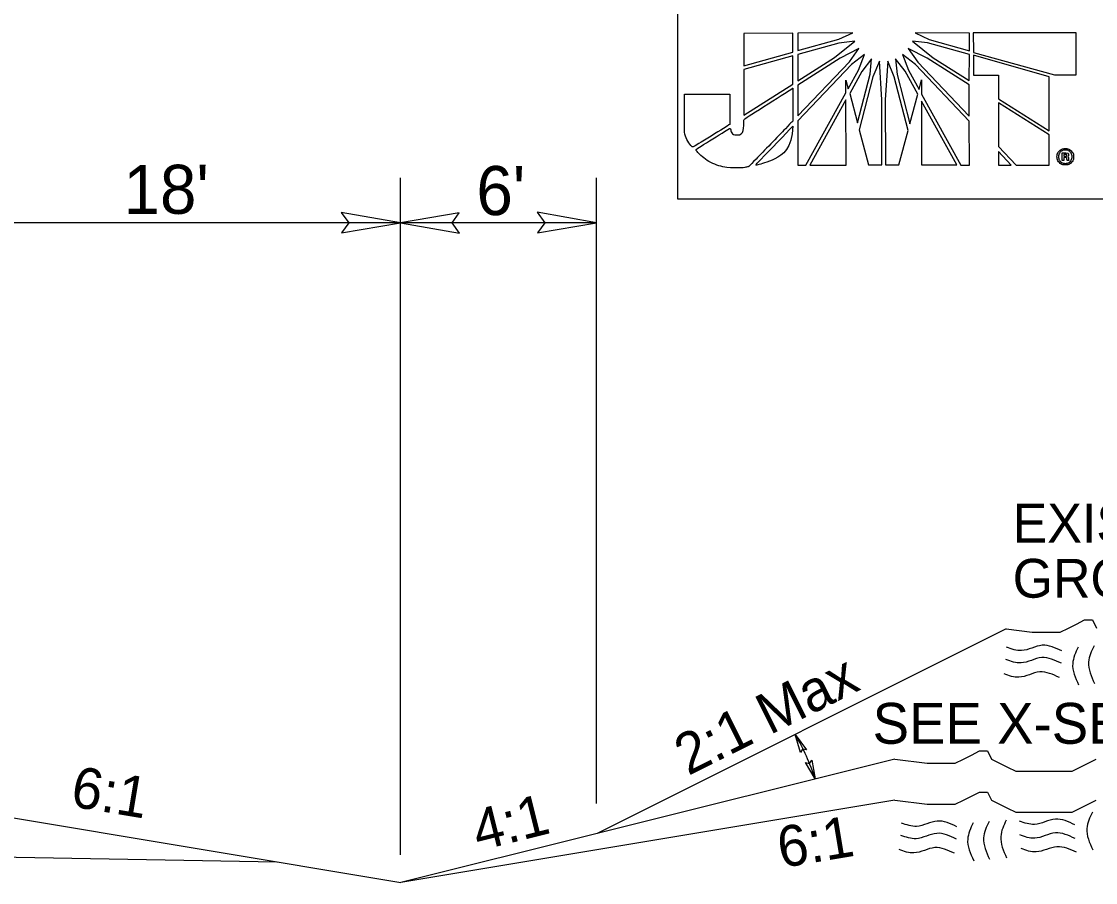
# Model space of a CAD drawing. Extents: x 2294455 to 2294795, y 719276 to 719941.
# Drawn here: x 2294722.83 to 2294763.9, y 719649.46 to 719682.39 of the extents above; entities that cross this region are included whole.
import ezdxf

# ---------------------------------------------------------------- set-up
doc = ezdxf.new("R2010")
doc.units = 0
for name, color, linetype in [('Old_Level_1', 7, 'Continuous'), ('Old_Level_11', 7, 'Continuous'), ('Old_Level_2', 7, 'Continuous'), ('Old_Level_3', 7, 'Continuous'), ('Typical Hinge Slope Arterial CELL', 7, 'Continuous'), ('Typical Hinge Slope Interstate CELL', 7, 'Continuous'), ('Typical Terminator CELL', 7, 'Continuous')]:
    doc.layers.add(name, color=color, linetype=linetype)

msp = doc.modelspace()

# ---------------------------------------------------------------- linework, layer by layer
at = {"layer": 'Old_Level_1'}
for p, q in [((2294752.321, 719681.935), (2294750.449, 719681.933)), ((2294750.449, 719681.933), (2294750.45, 719680.691)), ((2294752.322, 719681.212), (2294752.321, 719681.935)), ((2294754.623, 719681.947), (2294752.516, 719681.945)), ((2294752.516, 719681.945), (2294752.517, 719681.274)), ((2294752.517, 719681.274), (2294754.086, 719681.708)), ((2294754.086, 719681.708), (2294754.623, 719681.947)), ((2294759.084, 719681.942), (2294757.008, 719681.949)), ((2294757.008, 719681.949), (2294757.534, 719681.702)), ((2294757.534, 719681.702), (2294759.085, 719681.268)), ((2294759.085, 719681.268), (2294759.084, 719681.942)), ((2294763.165, 719681.955), (2294759.229, 719681.951)), ((2294759.229, 719681.951), (2294759.23, 719681.228)), ((2294763.167, 719680.342), (2294763.165, 719681.955)), ((2294754.086, 719681.563), (2294752.517, 719681.129)), ((2294753.923, 719681.007), (2294754.697, 719681.638)), ((2294754.697, 719681.638), (2294754.086, 719681.563)), ((2294754.852, 719681.348), (2294754.139, 719680.985)), ((2294754.491, 719680.84), (2294754.852, 719681.348)), ((2294756.74, 719681.349), (2294757.102, 719680.834)), ((2294757.463, 719680.989), (2294756.74, 719681.349)), ((2294756.903, 719681.64), (2294757.689, 719680.998)), ((2294757.481, 719681.566), (2294756.903, 719681.64)), ((2294759.085, 719681.126), (2294757.481, 719681.566)), ((2294750.45, 719680.691), (2294752.322, 719681.212)), ((2294752.322, 719681.076), (2294750.45, 719680.549)), ((2294752.323, 719679.992), (2294752.322, 719681.076)), ((2294752.517, 719681.129), (2294752.518, 719680.116)), ((2294752.518, 719680.116), (2294753.923, 719681.007)), ((2294754.139, 719680.985), (2294752.518, 719679.952)), ((2294755.069, 719681.122), (2294754.572, 719680.739)), ((2294754.841, 719680.523), (2294755.069, 719681.122)), ((2294755.338, 719680.956), (2294754.967, 719680.479)), ((2294755.286, 719680.378), (2294755.338, 719680.956)), ((2294755.647, 719680.872), (2294755.391, 719680.273)), ((2294755.728, 719679.396), (2294755.647, 719680.872)), ((2294755.956, 719680.873), (2294755.861, 719679.396)), ((2294756.203, 719680.274), (2294755.956, 719680.873)), ((2294756.255, 719680.956), (2294756.318, 719680.357)), ((2294756.617, 719680.481), (2294756.255, 719680.956)), ((2294756.521, 719681.124), (2294756.75, 719680.524)), ((2294757.018, 719680.741), (2294756.521, 719681.124)), ((2294759.074, 719679.967), (2294757.463, 719680.989)), ((2294757.689, 719680.998), (2294759.074, 719680.134)), ((2294759.074, 719680.134), (2294759.085, 719681.126)), ((2294759.23, 719681.228), (2294759.23, 719681.206)), ((2294759.23, 719681.206), (2294762.33, 719680.341)), ((2294759.23, 719681.095), (2294759.23, 719681.083)), ((2294762.132, 719680.27), (2294759.23, 719681.095)), ((2294759.23, 719681.083), (2294759.231, 719680.329)), ((2294750.45, 719680.549), (2294750.452, 719678.804)), ((2294752.519, 719678.784), (2294754.491, 719680.84)), ((2294754.572, 719680.739), (2294752.519, 719678.586)), ((2294754.449, 719679.809), (2294754.841, 719680.523)), ((2294754.967, 719680.479), (2294754.502, 719679.632)), ((2294757.103, 719679.604), (2294756.617, 719680.481)), ((2294756.75, 719680.524), (2294757.152, 719679.78)), ((2294759.075, 719678.574), (2294757.018, 719680.741)), ((2294757.102, 719680.834), (2294759.075, 719678.769)), ((2294754.356, 719679.654), (2294754.356, 719680.148)), ((2294754.356, 719680.148), (2294754.449, 719679.809)), ((2294754.802, 719678.508), (2294755.286, 719680.378)), ((2294755.391, 719680.273), (2294754.864, 719678.249)), ((2294756.743, 719678.22), (2294756.203, 719680.274)), ((2294756.318, 719680.357), (2294756.804, 719678.467)), ((2294757.152, 719679.78), (2294757.248, 719680.151)), ((2294757.248, 719680.151), (2294757.248, 719679.604)), ((2294759.231, 719680.329), (2294760.192, 719680.33)), ((2294760.192, 719680.33), (2294760.193, 719679.431)), ((2294762.134, 719678.203), (2294762.132, 719680.27)), ((2294762.33, 719680.341), (2294763.167, 719680.342)), ((2294750.452, 719678.804), (2294752.323, 719679.992)), ((2294752.518, 719679.952), (2294752.519, 719678.784)), ((2294752.83, 719676.887), (2294754.356, 719679.654)), ((2294759.075, 719678.769), (2294759.074, 719679.967)), ((2294754.357, 719679.385), (2294752.975, 719676.888)), ((2294754.371, 719676.889), (2294754.357, 719679.385)), ((2294754.502, 719679.632), (2294754.802, 719678.508)), ((2294755.731, 719676.899), (2294755.728, 719679.396)), ((2294755.861, 719679.396), (2294755.864, 719676.9)), ((2294756.804, 719678.467), (2294757.103, 719679.604)), ((2294757.248, 719679.604), (2294758.746, 719676.893)), ((2294758.592, 719676.902), (2294757.248, 719679.335)), ((2294757.248, 719679.335), (2294757.251, 719676.901)), ((2294760.193, 719679.431), (2294762.134, 719678.203)), ((2294760.193, 719679.276), (2294760.194, 719677.602)), ((2294762.134, 719678.058), (2294760.193, 719679.276)), ((2294752.519, 719678.586), (2294752.521, 719676.887)), ((2294759.077, 719676.893), (2294759.075, 719678.574)), ((2294754.864, 719678.249), (2294755.218, 719676.899)), ((2294756.383, 719676.9), (2294756.743, 719678.22)), ((2294762.135, 719676.896), (2294762.134, 719678.058)), ((2294760.194, 719677.602), (2294760.866, 719676.895)), ((2294760.68, 719676.895), (2294760.195, 719677.42)), ((2294760.195, 719677.42), (2294760.195, 719676.894)), ((2294762.628, 719677.073), (2294762.628, 719677.36)), ((2294762.628, 719677.36), (2294762.745, 719677.36)), ((2294762.745, 719677.305), (2294762.693, 719677.305)), ((2294762.693, 719677.305), (2294762.693, 719677.237)), ((2294762.693, 719677.237), (2294762.745, 719677.237)), ((2294762.745, 719677.185), (2294762.693, 719677.185)), ((2294762.693, 719677.185), (2294762.693, 719677.074)), ((2294762.745, 719677.529), (2294762.745, 719677.469)), ((2294762.745, 719677.469), (2294762.745, 719677.529)), ((2294762.745, 719677.36), (2294762.745, 719677.305)), ((2294762.745, 719677.305), (2294762.745, 719677.36)), ((2294762.745, 719677.36), (2294762.763, 719677.36)), ((2294762.753, 719677.305), (2294762.745, 719677.305)), ((2294762.745, 719677.237), (2294762.745, 719677.185)), ((2294762.745, 719677.185), (2294762.745, 719677.237)), ((2294762.745, 719677.237), (2294762.748, 719677.237)), ((2294762.748, 719677.185), (2294762.745, 719677.185)), ((2294752.521, 719676.887), (2294752.83, 719676.887)), ((2294752.975, 719676.888), (2294754.371, 719676.889)), ((2294755.218, 719676.899), (2294755.731, 719676.899)), ((2294755.864, 719676.9), (2294756.383, 719676.9)), ((2294757.251, 719676.901), (2294758.592, 719676.902)), ((2294758.746, 719676.893), (2294759.077, 719676.893)), ((2294760.195, 719676.894), (2294760.68, 719676.895)), ((2294760.866, 719676.895), (2294762.135, 719676.896)), ((2294762.693, 719677.074), (2294762.628, 719677.073)), ((2294762.745, 719676.962), (2294762.745, 719676.899)), ((2294762.745, 719676.899), (2294762.745, 719676.962)), ((2294762.745, 719676.962), (2294762.748, 719676.962)), ((2294762.748, 719676.899), (2294762.745, 719676.899)), ((2294710.861, 719650.642), (2294732.6, 719650.251))]:
    msp.add_line(p, q, dxfattribs=at)
msp.add_lwpolyline([(2294747.917, 719675.6), (2294787.924, 719675.6), (2294787.924, 719682.819), (2294747.917, 719682.819)], close=True, dxfattribs=at)
for points in [[(2294750.45, 719680.691), (2294752.322, 719681.212), (2294752.321, 719681.935), (2294750.449, 719681.933), (2294750.45, 719680.691)], [(2294754.086, 719681.708), (2294754.623, 719681.947), (2294752.516, 719681.945), (2294752.517, 719681.274), (2294754.086, 719681.708)], [(2294757.534, 719681.702), (2294759.085, 719681.268), (2294759.084, 719681.942), (2294757.008, 719681.949), (2294757.534, 719681.702)], [(2294763.165, 719681.955), (2294759.229, 719681.951), (2294759.23, 719681.228), (2294759.23, 719681.206), (2294762.33, 719680.341), (2294763.167, 719680.342), (2294763.165, 719681.955)], [(2294752.517, 719681.129), (2294752.518, 719680.116), (2294753.923, 719681.007), (2294754.697, 719681.638), (2294754.086, 719681.563), (2294752.517, 719681.129)], [(2294752.518, 719679.952), (2294752.519, 719678.784), (2294754.491, 719680.84), (2294754.852, 719681.348), (2294754.139, 719680.985), (2294752.518, 719679.952)], [(2294756.74, 719681.349), (2294757.102, 719680.834), (2294759.075, 719678.769), (2294759.074, 719679.967), (2294757.463, 719680.989), (2294756.74, 719681.349)], [(2294756.903, 719681.64), (2294757.689, 719680.998), (2294759.074, 719680.134), (2294759.085, 719681.126), (2294757.481, 719681.566), (2294756.903, 719681.64)], [(2294750.452, 719678.804), (2294752.323, 719679.992), (2294752.322, 719681.076), (2294750.45, 719680.549), (2294750.452, 719678.804)], [(2294755.069, 719681.122), (2294754.572, 719680.739), (2294752.519, 719678.586), (2294752.521, 719676.887), (2294752.83, 719676.887), (2294754.356, 719679.654), (2294754.356, 719680.148), (2294754.449, 719679.809), (2294754.841, 719680.523), (2294755.069, 719681.122)], [(2294755.338, 719680.956), (2294754.967, 719680.479), (2294754.502, 719679.632), (2294754.802, 719678.508), (2294755.286, 719680.378), (2294755.338, 719680.956)], [(2294755.391, 719680.273), (2294754.864, 719678.249), (2294755.218, 719676.899), (2294755.731, 719676.899), (2294755.728, 719679.396), (2294755.647, 719680.872), (2294755.391, 719680.273)], [(2294755.956, 719680.873), (2294755.861, 719679.396), (2294755.864, 719676.9), (2294756.383, 719676.9), (2294756.743, 719678.22), (2294756.203, 719680.274), (2294755.956, 719680.873)], [(2294756.255, 719680.956), (2294756.318, 719680.357), (2294756.804, 719678.467), (2294757.103, 719679.604), (2294756.617, 719680.481), (2294756.255, 719680.956)], [(2294756.521, 719681.124), (2294756.75, 719680.524), (2294757.152, 719679.78), (2294757.248, 719680.151), (2294757.248, 719679.604), (2294758.746, 719676.893), (2294759.077, 719676.893), (2294759.075, 719678.574), (2294757.018, 719680.741), (2294756.521, 719681.124)], [(2294759.23, 719681.095), (2294759.23, 719681.083), (2294759.231, 719680.329), (2294760.192, 719680.33), (2294760.193, 719679.431), (2294762.134, 719678.203), (2294762.132, 719680.27), (2294759.23, 719681.095)], [(2294752.975, 719676.888), (2294754.371, 719676.889), (2294754.357, 719679.385), (2294752.975, 719676.888)], [(2294757.251, 719676.901), (2294758.592, 719676.902), (2294757.248, 719679.335), (2294757.251, 719676.901)], [(2294760.193, 719679.276), (2294760.194, 719677.602), (2294760.866, 719676.895), (2294762.135, 719676.896), (2294762.134, 719678.058), (2294760.193, 719679.276), (2294760.193, 719679.276)], [(2294760.195, 719676.894), (2294760.195, 719676.894), (2294760.68, 719676.895), (2294760.195, 719677.42), (2294760.195, 719676.894)], [(2294762.87, 719677.141), (2294762.87, 719677.126), (2294762.873, 719677.115), (2294762.873, 719677.105), (2294762.88, 719677.074), (2294762.821, 719677.074)]]:
    msp.add_lwpolyline(points, dxfattribs=at)
for points, degree in [([(2294750.184, 719678.047), (2294750.073, 719678.046), (2294749.977, 719678.108), (2294749.937, 719678.315), (2294749.937, 719678.315), (2294748.593, 719677.483), (2294748.593, 719677.483), (2294749.008, 719677.047), (2294749.669, 719676.789), (2294750.228, 719676.789), (2294750.374, 719676.789), (2294750.485, 719676.802), (2294750.639, 719676.833), (2294750.639, 719676.833), (2294752.324, 719678.577), (2294752.324, 719678.577), (2294752.324, 719678.577), (2294752.323, 719679.837), (2294752.323, 719679.837), (2294752.323, 719679.837), (2294750.452, 719678.646), (2294750.452, 719678.646), (2294750.453, 719678.173), (2294750.338, 719678.047), (2294750.184, 719678.047)], 3), ([(2294750.184, 719678.047), (2294750.073, 719678.046), (2294749.977, 719678.108), (2294749.937, 719678.315), (2294749.937, 719678.315), (2294748.593, 719677.483), (2294748.593, 719677.483), (2294749.008, 719677.047), (2294749.669, 719676.789), (2294750.228, 719676.789), (2294750.374, 719676.789), (2294750.485, 719676.802), (2294750.639, 719676.833), (2294750.639, 719676.833), (2294752.324, 719678.577), (2294752.324, 719678.577), (2294752.324, 719678.577), (2294752.323, 719679.837), (2294752.323, 719679.837), (2294752.323, 719679.837), (2294750.452, 719678.646), (2294750.452, 719678.646), (2294750.453, 719678.173), (2294750.338, 719678.047), (2294750.184, 719678.047)], 3), ([(2294749.914, 719679.606), (2294749.914, 719679.606), (2294748.18, 719679.605), (2294748.18, 719679.605), (2294748.18, 719679.605), (2294748.181, 719678.52), (2294748.181, 719678.52), (2294748.181, 719678.52), (2294748.182, 719678.406), (2294748.182, 719678.406), (2294748.182, 719678.066), (2294748.293, 719677.798), (2294748.491, 719677.572), (2294748.491, 719677.572), (2294749.915, 719678.439), (2294749.915, 719678.46), (2294749.915, 719678.46), (2294749.914, 719679.606), (2294749.914, 719679.606)], 3), ([(2294752.325, 719678.379), (2294752.325, 719678.379), (2294750.868, 719676.873), (2294750.868, 719676.873), (2294751.581, 719677.05), (2294752.291, 719677.523), (2294752.325, 719678.379)], 3), ([(2294762.745, 719676.899), (2294762.66, 719676.899), (2294762.584, 719676.93), (2294762.521, 719676.993), (2294762.459, 719677.052), (2294762.428, 719677.128), (2294762.428, 719677.216), (2294762.428, 719677.305), (2294762.459, 719677.38), (2294762.521, 719677.438), (2294762.583, 719677.498), (2294762.656, 719677.529), (2294762.745, 719677.529)], 3), ([(2294762.745, 719677.469), (2294762.675, 719677.469), (2294762.615, 719677.446), (2294762.565, 719677.399), (2294762.516, 719677.349), (2294762.49, 719677.287), (2294762.49, 719677.216), (2294762.49, 719677.146), (2294762.516, 719677.084), (2294762.566, 719677.034), (2294762.615, 719676.985), (2294762.675, 719676.962), (2294762.745, 719676.962)], 3), ([(2294762.745, 719677.529), (2294762.833, 719677.529), (2294762.909, 719677.498), (2294762.971, 719677.438), (2294763.034, 719677.381), (2294763.065, 719677.305), (2294763.065, 719677.217)], 3), ([(2294762.748, 719676.962), (2294762.818, 719676.962), (2294762.878, 719676.985), (2294762.927, 719677.035), (2294762.977, 719677.084), (2294763.003, 719677.147), (2294763.003, 719677.217), (2294763.003, 719677.287), (2294762.976, 719677.35), (2294762.927, 719677.399), (2294762.878, 719677.446), (2294762.818, 719677.469), (2294762.745, 719677.469)], 3), ([(2294762.748, 719677.237), (2294762.789, 719677.238), (2294762.81, 719677.251), (2294762.81, 719677.274), (2294762.81, 719677.295), (2294762.792, 719677.305), (2294762.753, 719677.305)], 3), ([(2294763.065, 719677.217), (2294763.065, 719677.128), (2294763.034, 719677.053), (2294762.974, 719676.991), (2294762.912, 719676.931), (2294762.836, 719676.899), (2294762.748, 719676.899)], 3), ([(2294762.797, 719677.175), (2294762.789, 719677.18), (2294762.774, 719677.185), (2294762.748, 719677.185)], 2), ([(2294762.763, 719677.36), (2294762.836, 719677.36), (2294762.872, 719677.331), (2294762.872, 719677.274), (2294762.872, 719677.248), (2294762.862, 719677.227), (2294762.839, 719677.212)], 3), ([(2294762.821, 719677.074), (2294762.813, 719677.089), (2294762.808, 719677.105), (2294762.808, 719677.126), (2294762.808, 719677.152), (2294762.805, 719677.167), (2294762.797, 719677.175)], 3), ([(2294762.839, 719677.212), (2294762.857, 719677.201), (2294762.867, 719677.178), (2294762.87, 719677.141)], 2)]:
    msp.add_open_spline(points, degree=degree, dxfattribs=at)
at = {"layer": 'Old_Level_11'}
for p, q in [((2294737.32, 719650.522), (2294737.32, 719676.409)), ((2294744.818, 719652.477), (2294744.818, 719676.409)), ((2294737.32, 719674.689), (2294718.57, 719674.688)), ((2294744.818, 719674.689), (2294737.32, 719674.689))]:
    msp.add_line(p, q, dxfattribs=at)
for points in [[(2294735.07, 719674.301), (2294737.32, 719674.689), (2294735.057, 719675.088), (2294735.345, 719674.689)], [(2294739.57, 719675.076), (2294737.32, 719674.689), (2294739.582, 719674.289), (2294739.295, 719674.689)], [(2294742.568, 719674.301), (2294744.818, 719674.689), (2294742.555, 719675.089), (2294742.843, 719674.689)]]:
    msp.add_lwpolyline(points, close=True, dxfattribs=at)
at = {"layer": 'Old_Level_2'}
for points in [[(2294762.618, 719658.316), (2294761.864, 719658.531), (2294761.073, 719658.328), (2294760.498, 719658.455)], [(2294762.618, 719658.316), (2294761.864, 719658.531), (2294761.073, 719658.328), (2294760.498, 719658.455)], [(2294763.24, 719658.459), (2294763.028, 719657.837), (2294763.257, 719657.016)], [(2294763.24, 719658.459), (2294763.028, 719657.837), (2294763.257, 719657.016)], [(2294763.847, 719658.514), (2294763.635, 719657.892), (2294763.861, 719657.068)], [(2294763.847, 719658.514), (2294763.635, 719657.892), (2294763.861, 719657.068)], [(2294762.598, 719657.844), (2294761.845, 719658.061), (2294761.053, 719657.856), (2294760.478, 719657.985)], [(2294762.598, 719657.844), (2294761.845, 719658.061), (2294761.053, 719657.856), (2294760.478, 719657.985)], [(2294762.522, 719657.299), (2294761.77, 719657.513), (2294760.974, 719657.31), (2294760.402, 719657.44)], [(2294762.522, 719657.299), (2294761.77, 719657.513), (2294760.974, 719657.31), (2294760.402, 719657.44)], [(2294763.781, 719652.152), (2294763.567, 719651.53), (2294763.796, 719650.708)], [(2294763.781, 719652.152), (2294763.567, 719651.53), (2294763.796, 719650.708)], [(2294758.603, 719651.596), (2294757.849, 719651.811), (2294757.058, 719651.608), (2294756.483, 719651.735)], [(2294758.603, 719651.596), (2294757.849, 719651.811), (2294757.058, 719651.608), (2294756.483, 719651.735)], [(2294759.225, 719651.74), (2294759.013, 719651.118), (2294759.242, 719650.296)], [(2294759.225, 719651.74), (2294759.013, 719651.118), (2294759.242, 719650.296)], [(2294759.831, 719651.794), (2294759.62, 719651.172), (2294759.846, 719650.348)], [(2294759.831, 719651.794), (2294759.62, 719651.172), (2294759.846, 719650.348)], [(2294760.487, 719651.845), (2294760.278, 719651.225), (2294760.502, 719650.401)], [(2294760.487, 719651.845), (2294760.278, 719651.225), (2294760.502, 719650.401)], [(2294763.116, 719651.667), (2294762.367, 719651.884), (2294761.568, 719651.681), (2294760.998, 719651.81)], [(2294763.116, 719651.667), (2294762.367, 719651.884), (2294761.568, 719651.681), (2294760.998, 719651.81)], [(2294758.583, 719651.124), (2294757.829, 719651.341), (2294757.038, 719651.136), (2294756.463, 719651.265)], [(2294758.583, 719651.124), (2294757.829, 719651.341), (2294757.038, 719651.136), (2294756.463, 719651.265)], [(2294763.12, 719651.145), (2294762.367, 719651.357), (2294761.575, 719651.154), (2294761.003, 719651.283)], [(2294763.12, 719651.145), (2294762.367, 719651.357), (2294761.575, 719651.154), (2294761.003, 719651.283)], [(2294758.506, 719650.579), (2294757.755, 719650.794), (2294756.959, 719650.591), (2294756.387, 719650.72)], [(2294758.506, 719650.579), (2294757.755, 719650.794), (2294756.959, 719650.591), (2294756.387, 719650.72)], [(2294763.179, 719650.616), (2294762.427, 719650.828), (2294761.629, 719650.63), (2294761.057, 719650.757)], [(2294763.179, 719650.616), (2294762.427, 719650.828), (2294761.629, 719650.63), (2294761.057, 719650.757)]]:
    msp.add_spline(points, degree=3, dxfattribs=at)
at = {"layer": 'Typical Hinge Slope Arterial CELL'}
for p, q in [((2294760.491, 719659.161), (2294744.841, 719651.336)), ((2294756.229, 719654.183), (2294744.841, 719651.336)), ((2294756.229, 719652.609), (2294737.342, 719649.461)), ((2294744.841, 719651.336), (2294737.342, 719649.461))]:
    msp.add_line(p, q, dxfattribs=at)
for points in [[(2294760.491, 719659.161), (2294761.476, 719659.038), (2294761.784, 719659.038), (2294762.247, 719659.038), (2294762.555, 719659.038), (2294762.863, 719659.191), (2294763.171, 719659.346), (2294763.479, 719659.501), (2294763.787, 719659.501), (2294763.941, 719659.191)], [(2294756.229, 719654.183), (2294757.461, 719654.029), (2294757.769, 719654.029), (2294758.232, 719654.029), (2294758.54, 719654.029), (2294758.848, 719654.183), (2294759.156, 719654.337), (2294759.464, 719654.492), (2294759.772, 719654.492), (2294759.926, 719654.183), (2294760.234, 719654.029), (2294760.542, 719653.875), (2294760.85, 719653.721), (2294761.158, 719653.721), (2294761.466, 719653.721), (2294761.774, 719653.721), (2294762.082, 719653.721), (2294762.39, 719653.721), (2294762.698, 719653.721), (2294763.006, 719653.721), (2294763.314, 719653.875), (2294763.622, 719654.029), (2294763.93, 719654.183)], [(2294756.229, 719652.609), (2294757.461, 719652.456), (2294757.769, 719652.456), (2294758.232, 719652.456), (2294758.54, 719652.456), (2294758.848, 719652.609), (2294759.156, 719652.764), (2294759.464, 719652.918), (2294759.772, 719652.918), (2294759.926, 719652.609), (2294760.234, 719652.456), (2294760.542, 719652.301), (2294760.85, 719652.148), (2294761.158, 719652.148), (2294761.466, 719652.148), (2294761.774, 719652.148), (2294762.082, 719652.148), (2294762.39, 719652.148), (2294762.698, 719652.148), (2294763.006, 719652.148), (2294763.314, 719652.301), (2294763.622, 719652.456), (2294763.93, 719652.609)]]:
    msp.add_lwpolyline(points, dxfattribs=at)
at = {"layer": 'Typical Hinge Slope Interstate CELL'}
msp.add_line((2294718.592, 719652.586), (2294737.342, 719649.461), dxfattribs=at)
msp.add_arc((2294744.841, 719650.711), 8.77, 18.0001, 30.219, dxfattribs=at)
at = {"layer": 'Typical Terminator CELL'}
for points in [[(2294752.621, 719654.428), (2294752.419, 719655.125), (2294752.848, 719654.534), (2294752.694, 719654.56)], [(2294753.052, 719654.135), (2294753.182, 719653.421), (2294752.816, 719654.053), (2294752.967, 719654.011)]]:
    msp.add_lwpolyline(points, close=True, dxfattribs=at)

# ---------------------------------------------------------------- texts
at = {"layer": 'Old_Level_1'}
for s, height, p in [('EXISTING', 1.4844, (2294760.733, 719662.463)), ('GROUND', 1.4844, (2294760.733, 719660.353)), ('SEE X-SECTIONS', 1.5625, (2294755.377, 719654.767))]:
    msp.add_text(s, height=height, rotation=360, dxfattribs=at).set_placement(p)
at = {"layer": 'Old_Level_3'}
for s, p in [("18'", (2294726.733, 719675.026)), ("6'", (2294740.228, 719674.982))]:
    msp.add_text(s, height=1.875, rotation=0.1671, dxfattribs=at).set_placement(p)
at = {"layer": 'Typical Hinge Slope Arterial CELL'}
msp.add_text('4:1', height=1.5625, rotation=14.0362, dxfattribs=at).set_placement((2294740.303, 719650.66))
at = {"layer": 'Typical Hinge Slope Interstate CELL'}
for s, rotation, p in [('2:1 Max', 26.5651, (2294748.321, 719653.529)), ('6:1', 350.5377, (2294724.661, 719652.383)), ('6:1', 9.4623, (2294751.878, 719650.013))]:
    msp.add_text(s, height=1.5625, rotation=rotation, dxfattribs=at).set_placement(p)

doc.saveas('drawing.dxf')
